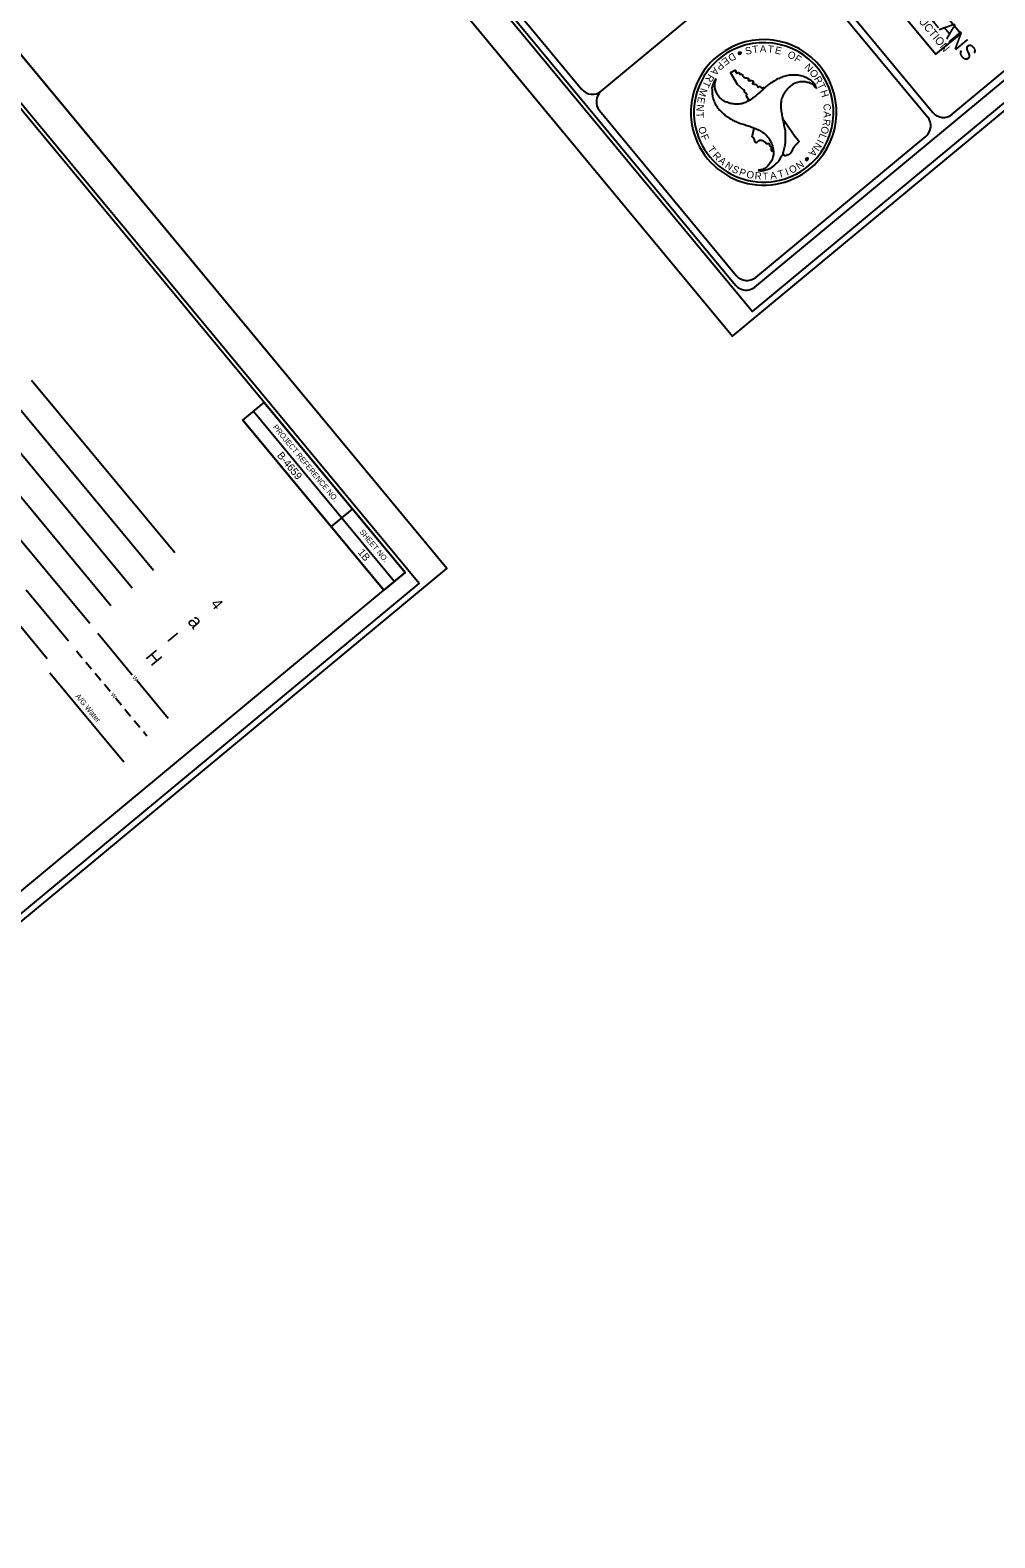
# Model space of a CAD drawing. Extents: x 2054826 to 2060231, y 685508 to 690809.
# Drawn here: x 2058198 to 2059246, y 686007 to 687645 of the extents above; entities that cross this region are included whole.
import ezdxf

# ---------------------------------------------------------------- set-up
doc = ezdxf.new("R2010")
doc.units = 0
for name, color, linetype in [('Sheet Cutting Line CELL', 7, 'Continuous'), ('Sheet Data Field CELL', 7, 'Continuous'), ('Sheet Plot Border Inside CELL', 7, 'Continuous'), ('Sheet Plot Border Outside CELL', 7, 'Continuous'), ('Sheet Sticker Preliminary CELL', 7, 'Continuous'), ('Sheet Symbology CELL', 7, 'Continuous'), ('Sheet Title CELL', 7, 'Continuous')]:
    doc.layers.add(name, color=color, linetype=linetype)

msp = doc.modelspace()

# ---------------------------------------------------------------- linework, layer by layer
at = {"layer": 'Sheet Cutting Line CELL'}
for p, q in [((2057348.7, 689256.9), (2058961.2, 687312.4)), ((2058650.7, 687059.8), (2057038.3, 689004.2))]:
    msp.add_line(p, q, dxfattribs=at)
at = {"layer": 'Sheet Plot Border Inside CELL'}
for points in [[(2057387.1, 689263.3), (2058982.8, 687339.1), (2060201, 688349.4), (2058605.4, 690273.6)], [(2055806.5, 687957.4), (2057402.2, 686033.2), (2058620.5, 687043.5), (2057024.8, 688967.7)]]:
    msp.add_lwpolyline(points, close=True, dxfattribs=at)
at = {"layer": 'Sheet Plot Border Outside CELL'}
for points in [[(2060231.3, 688365.7), (2058618.8, 690310.1), (2057348.7, 689256.9), (2058961.2, 687312.4)], [(2055768.2, 687951), (2057380.6, 686006.5), (2058650.7, 687059.8), (2057038.3, 689004.2)]]:
    msp.add_lwpolyline(points, close=True, dxfattribs=at)
at = {"layer": 'Sheet Sticker Preliminary CELL'}
msp.add_lwpolyline([(2059041.1, 687788.3), (2059068.2, 687810.8), (2059209, 687641.1), (2059181.8, 687618.6)], close=True, dxfattribs=at)
at = {"layer": 'Sheet Symbology CELL'}
for p, q in [((2058332, 687057.5), (2058161.5, 687263.1)), ((2058355.1, 687076.7), (2058199.6, 687264.2)), ((2058308.9, 687038.4), (2058138.5, 687243.9)), ((2058440.7, 687230.6), (2058594, 687045.8)), ((2058285.8, 687019.2), (2058127.1, 687210.6)), ((2058429.2, 687221.1), (2058582.4, 687036.3)), ((2058262.7, 687000.1), (2058165.9, 687116.8)), ((2058548.1, 687124.7), (2058525, 687105.6)), ((2058216.5, 686961.8), (2058123, 687074.6)), ((2058239.6, 686980.9), (2058193.7, 687036.4)), ((2058271.4, 686989.7), (2058309, 686944.3)), ((2058248.4, 686970.3), (2058254.6, 686962.8)), ((2058219.4, 686946.6), (2058299.8, 686849.6)), ((2058258.5, 686958.2), (2058264.7, 686950.7)), ((2058268.5, 686946.1), (2058274.8, 686938.6)), ((2058278.6, 686934), (2058284.8, 686926.4)), ((2058313.8, 686938.5), (2058348, 686897.3)), ((2058290.9, 686919.1), (2058297.2, 686911.6)), ((2058301, 686906.9), (2058307.2, 686899.4)), ((2058311, 686894.8), (2058317.3, 686887.3)), ((2058321.1, 686882.7), (2058324.9, 686878.1))]:
    msp.add_line(p, q, dxfattribs=at)
for points in [[(2058605.6, 687055.5), (2057169.3, 688787.4), (2055958.1, 687783), (2057394.3, 686051.1)], [(2058452.3, 687240.2), (2058605.6, 687055.5), (2058582.4, 687036.3), (2058429.2, 687221.1)]]:
    msp.add_lwpolyline(points, close=True, dxfattribs=at)
at = {"layer": 'Sheet Title CELL'}
for p, q in [((2057819.1, 689194.8), (2059178.8, 687555.2)), ((2058818.5, 687578.5), (2059003.2, 687731.7)), ((2059024.4, 687729.7), (2059173, 687550.5)), ((2058967.3, 687619.8), (2058968.6, 687620.2)), ((2058968.6, 687619.4), (2058967.3, 687619.8)), ((2058968.5, 687618), (2058968.6, 687619.4)), ((2058969.4, 687619), (2058968.5, 687618)), ((2058968.6, 687620.2), (2058968.7, 687621.6)), ((2058968.7, 687621.6), (2058969.5, 687620.4)), ((2058970.6, 687618.5), (2058969.4, 687619)), ((2058969.5, 687620.4), (2058970.7, 687620.7)), ((2058970.7, 687620.7), (2058969.9, 687619.7)), ((2058969.9, 687619.7), (2058970.6, 687618.5)), ((2058959.1, 687598.6), (2058963.2, 687601)), ((2058966.6, 687585.6), (2058959.1, 687598.6)), ((2058973.3, 687579.7), (2058966.6, 687585.6)), ((2058979.2, 687568.2), (2058976, 687573.6)), ((2059052.5, 687581.5), (2059052.3, 687581.6)), ((2059052.5, 687581.5), (2059052.3, 687581.6)), ((2058982.3, 687528.8), (2058984.8, 687538.3)), ((2058984.8, 687538.3), (2058984.8, 687538.3)), ((2059015.9, 687548.6), (2059015.9, 687548.6)), ((2059041.4, 687505), (2059040.1, 687504.6)), ((2059040.1, 687504.6), (2059041.3, 687504.2)), ((2059041.3, 687504.2), (2059041.2, 687502.8)), ((2059041.2, 687502.8), (2059042.1, 687503.8)), ((2059041.5, 687506.4), (2059041.4, 687505)), ((2059042.2, 687505.2), (2059041.5, 687506.4)), ((2059042.1, 687503.8), (2059043.4, 687503.4)), ((2059043.5, 687505.5), (2059042.2, 687505.2)), ((2059042.7, 687504.5), (2059043.5, 687505.5)), ((2059043.4, 687503.4), (2059042.7, 687504.5)), ((2059037, 687488.4), (2059037, 687488.4))]:
    msp.add_line(p, q, dxfattribs=at)
for points in [[(2057547.1, 689076.4), (2058964.2, 687367.5)], [(2058985.3, 687365.6), (2060174.6, 688351.8)], [(2059199.9, 687553.3), (2060164, 688352.8)], [(2058606.1, 687811.1), (2058797.4, 687580.4)], [(2058816.5, 687557.3), (2058965.2, 687378.1)], [(2058986.3, 687376.1), (2059171, 687529.3)]]:
    msp.add_lwpolyline(points, dxfattribs=at)
for centre, radius, start, end in [((2058995, 687555.4), 79.1, 302.0883, 122.0883), ((2058995, 687555.4), 79.1, 122.0883, 302.0883), ((2058995, 687555.4), 75.8, 122.0883, 302.0883), ((2058995, 687555.4), 75.8, 302.0883, 122.0883), ((2058809, 687590.1), 15, 219.6672, 309.6672), ((2058828.1, 687567), 15, 129.6672, 219.6672), ((2059364.7, 687776.9), 416.9, 207.7668, 207.8664), ((2059190.4, 687564.9), 15, 219.6672, 309.6672), ((2059364.7, 687776.9), 416.9, 213.2059, 217.4119), ((2059161.5, 687540.9), 15, 309.6672, 39.6672), ((2058976.8, 687387.7), 15, 219.6672, 309.6672), ((2058975.8, 687377.2), 15, 219.6672, 309.6672)]:
    msp.add_arc(centre, radius, start, end, dxfattribs=at)
for points in [[(2058963.2, 687601), (2058963.5, 687601.4), (2058964.3, 687601), (2058964.8, 687598.6), (2058966.2, 687598.2), (2058967, 687598.7), (2058968.2, 687598.5), (2058968.8, 687597), (2058971, 687596.8), (2058971.9, 687595.9), (2058973.4, 687593.6), (2058977.7, 687592.6), (2058978.6, 687591.6), (2058978.1, 687590.9), (2058978.4, 687590.1), (2058981.3, 687590.3), (2058981.8, 687590.2), (2058984, 687588.6), (2058983.9, 687587.8), (2058983, 687587.1), (2058983, 687586.6), (2058984, 687586.3), (2058985.7, 687586.1), (2058987.7, 687584.9), (2058988.7, 687582.8), (2058990.5, 687583.5), (2058993.5, 687582.1), (2058994.7, 687582.2), (2058995.8, 687582.7)], [(2058943.4, 687591.9), (2058942.2, 687590.5), (2058939.9, 687585.8), (2058938.9, 687580.3), (2058939, 687579.8), (2058938.9, 687576.7), (2058939.5, 687573.2), (2058941, 687567.5), (2058943.9, 687562.3), (2058945.2, 687560.1), (2058947.1, 687558), (2058951.2, 687553.9), (2058955.5, 687550.6), (2058960.9, 687547.3), (2058965.8, 687544.8), (2058971.3, 687542.9), (2058976.8, 687541.2), (2058982, 687539.3), (2058987.4, 687537.3), (2058992.4, 687534.7), (2058992.9, 687534.4), (2058997.8, 687530.7), (2059001.2, 687526.1), (2059003.7, 687521.3), (2059004.7, 687518.6), (2059005.1, 687515.4), (2059005.6, 687513.4), (2059005.5, 687509.4), (2059004.1, 687504.1), (2059001.4, 687499.6), (2058998.1, 687496), (2058993.8, 687493.5), (2058989, 687492.5)], [(2059052.3, 687581.6), (2059051.7, 687583.3), (2059048.8, 687587.7), (2059044.5, 687591.3), (2059044, 687591.5), (2059041.4, 687593.1), (2059038.1, 687594.3), (2059032.4, 687595.8), (2059026.4, 687596), (2059023.9, 687595.9), (2059021.2, 687595.4), (2059015.5, 687593.9), (2059010.5, 687591.8), (2059004.9, 687588.7), (2059000.3, 687585.7), (2058996, 687581.9), (2058991.7, 687578.1), (2058987.5, 687574.5), (2058983, 687570.8), (2058978.3, 687567.8), (2058977.8, 687567.5), (2058972.2, 687565.2), (2058966.4, 687564.4), (2058961, 687564.7), (2058958.3, 687565.2), (2058955.2, 687566.4), (2058953.3, 687567), (2058949.9, 687569.1), (2058945.9, 687573), (2058943.4, 687577.6), (2058941.9, 687582.2), (2058942, 687587.1), (2058943.4, 687591.9)], [(2058989, 687492.5), (2058990.7, 687492.1), (2058996, 687492.5), (2059001.2, 687494.4), (2059001.7, 687494.6), (2059004.3, 687496.2), (2059007.1, 687498.4), (2059011.3, 687502.5), (2059014.3, 687507.7), (2059015.6, 687509.8), (2059016.5, 687512.5), (2059018, 687518.2), (2059018.7, 687523.6), (2059018.8, 687529.9), (2059018.5, 687535.4), (2059017.4, 687541.1), (2059016.2, 687546.7), (2059015.2, 687552.1), (2059014.2, 687557.9), (2059014, 687563.5), (2059014, 687564), (2059014.8, 687570.1), (2059017, 687575.4), (2059020, 687580), (2059021.8, 687582), (2059024.4, 687584.2), (2059025.8, 687585.5), (2059029.3, 687587.4), (2059034.7, 687588.9), (2059040, 687588.8), (2059044.7, 687587.7), (2059048.9, 687585.2), (2059052.3, 687581.6), (2059052.5, 687581.5)], [(2058976, 687573.6), (2058976.6, 687574.7), (2058976.3, 687575.9), (2058974.7, 687576.8), (2058974.1, 687577.9), (2058974.2, 687579.6), (2058973.3, 687579.7)], [(2058996.1, 687582), (2058996, 687581.9), (2058991.7, 687578.1), (2058987.5, 687574.5), (2058983, 687570.8), (2058979.2, 687568.2)], [(2058984.8, 687538.3), (2058987.4, 687537.3), (2058992.4, 687534.7), (2058992.9, 687534.4), (2058997.8, 687530.7), (2059001.2, 687526.1), (2059003.7, 687521.3), (2059004.7, 687518.6), (2059005.1, 687515.4), (2059005.6, 687513.5)], [(2059016, 687510.8), (2059016.5, 687512.5), (2059018, 687518.2), (2059018.7, 687523.6), (2059018.8, 687529.9), (2059018.5, 687535.4), (2059017.4, 687541.1), (2059016.2, 687546.7), (2059015.9, 687548.6)], [(2059005.5, 687513.6), (2059004, 687513.4), (2059003.3, 687514.4), (2059003.6, 687517), (2059001.8, 687518.9), (2059001.7, 687520.3), (2059001.3, 687521), (2058998.4, 687521.3), (2058996.6, 687523.1), (2058991.8, 687525), (2058989.9, 687524.8), (2058986.8, 687522.5), (2058985.7, 687523), (2058985.2, 687524.1), (2058984.7, 687526.8), (2058982.3, 687528.8)], [(2059033.5, 687523.6), (2059029.7, 687519.9), (2059025.9, 687514.2), (2059023.9, 687510.9), (2059021.4, 687509.4), (2059018.1, 687508.1), (2059016, 687510.8)]]:
    msp.add_spline(points, degree=3, dxfattribs=at)

# ---------------------------------------------------------------- texts
at = {"layer": 'Sheet Data Field CELL'}
for s, p in [('B-4659', (2058465.7, 687182.4)), ('1B', (2058553.5, 687077.1))]:
    msp.add_text(s, height=8.1, rotation=309.6672, dxfattribs=at).set_placement(p)
at = {"layer": 'Sheet Sticker Preliminary CELL'}
for s, height, p in [('PRELIMINARY PLANS', 17.28, (2059062.5, 687793.4)), ('DO NOT USE FOR CONSTRUCTION', 8.64, (2059066.2, 687770.9))]:
    msp.add_text(s, height=height, rotation=309.6672, dxfattribs=at).set_placement(p)
at = {"layer": 'Sheet Symbology CELL'}
for s, height, p in [('PROJECT REFERENCE NO.', 6, (2058461.3, 687213.1)), ('SHEET NO.', 6, (2058555.5, 687099.3)), ('4', 12.4, (2058393.3, 687020.9)), ('a', 15.3, (2058368.2, 687001.9)), ('I', 14.1, (2058345.9, 686982.7)), ('H', 14.6, (2058322.5, 686963.6)), ('W', 4.5, (2058308.6, 686941.2)), ('A/G Water', 6, (2058246.7, 686920.7)), ('W', 4.5, (2058285.1, 686922.6))]:
    msp.add_text(s, height=height, rotation=309.6672, dxfattribs=at).set_placement(p)
at = {"layer": 'Sheet Title CELL'}
for s, height, rotation, p in [('D', 7.89, 209.9413, (2058961.9, 687620.7)), ('S', 7.88, 13.8446, (2058975.9, 687617.8)), ('T', 7.9, 7.4684, (2058983.2, 687619.6)), ('A', 7.91, 0.4161, (2058990.8, 687620.5)), ('T', 7.87, 353.3609, (2058999, 687620.6)), ('E', 7.86, 346.2453, (2059006.6, 687619.7)), ('O', 7.89, 334.3059, (2059020, 687615.7)), ('F', 7.9, 327.1591, (2059027.5, 687612)), ('A', 7.87, 230.3542, (2058941.2, 687605.1)), ('P', 7.89, 223.7616, (2058947.3, 687610.9)), ('E', 7.85, 216.2292, (2058954.1, 687616.1)), ('N', 7.89, 315.0721, (2059038.6, 687603.9)), ('O', 7.9, 307.574, (2059044.1, 687598.5)), ('T', 7.88, 244.0734, (2058930.7, 687590.5)), ('R', 7.88, 237.4228, (2058935.3, 687597.8)), ('R', 7.89, 300.9641, (2059049.2, 687591.9)), ('T', 7.9, 294.3144, (2059053, 687585.4)), ('E', 7.86, 258.7752, (2058923.9, 687572.8)), ('M', 7.86, 251.3084, (2058926.9, 687582.4)), ('H', 7.87, 287.2297, (2059056.2, 687578.3)), ('N', 7.9, 265.7467, (2058922.3, 687564.4)), ('T', 7.87, 272.5887, (2058921.7, 687555.6)), ('C', 7.86, 274.8874, (2059059.7, 687564.5)), ('A', 7.88, 267.3903, (2059060.3, 687556.7)), ('O', 7.88, 285.8924, (2058923.6, 687538.8)), ('O', 7.9, 253.9068, (2059058.8, 687541.1)), ('R', 7.88, 261.0264, (2059060, 687548.6)), ('F', 7.88, 293.0576, (2058926.3, 687529.7)), ('T', 7.86, 305.9669, (2058933.6, 687515.3)), ('N', 7.88, 237.9837, (2059052, 687523.4)), ('I', 7.9, 243.6838, (2059053.7, 687526.8)), ('L', 7.86, 247.6731, (2059056.5, 687533.1)), ('R', 7.89, 312.9235, (2058938.9, 687508.1)), ('A', 7.86, 319.6766, (2058945, 687501.9)), ('N', 7.89, 34.2965, (2059033.4, 687492.9)), ('A', 7.89, 230.5517, (2059047.8, 687516.9)), ('N', 7.86, 326.7082, (2058952.1, 687495.9)), ('S', 7.85, 333.9187, (2058959.7, 687491.2)), ('P', 7.88, 341.1106, (2058967.5, 687487.4)), ('O', 7.9, 347.8026, (2058975.6, 687484.7)), ('R', 7.9, 354.9917, (2058984.9, 687482.8)), ('T', 7.86, 1.0915, (2058993.6, 687482.1)), ('A', 7.9, 9.1785, (2059002.5, 687482.4)), ('T', 7.87, 16.2629, (2059011.7, 687484)), ('I', 7.9, 21.9128, (2059020.3, 687486.6)), ('O', 7.86, 27.0485, (2059024.9, 687488.5))]:
    msp.add_text(s, height=height, rotation=rotation, dxfattribs=at).set_placement(p)

doc.saveas('drawing.dxf')
